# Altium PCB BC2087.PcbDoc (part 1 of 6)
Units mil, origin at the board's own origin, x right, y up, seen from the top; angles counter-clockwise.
Board outline 7401.57 x 1181.1 mil, 6 copper layers (Top Copper, Signal Layer 1, Signal Layer 2, Signal Layer 3, Signal Layer 4, Bottom Copper), stack 62.874 mil thick; 302 components, 237 nets, 1184 pads, 867 vias.
Unrouted connection lines stored in the file: 315.
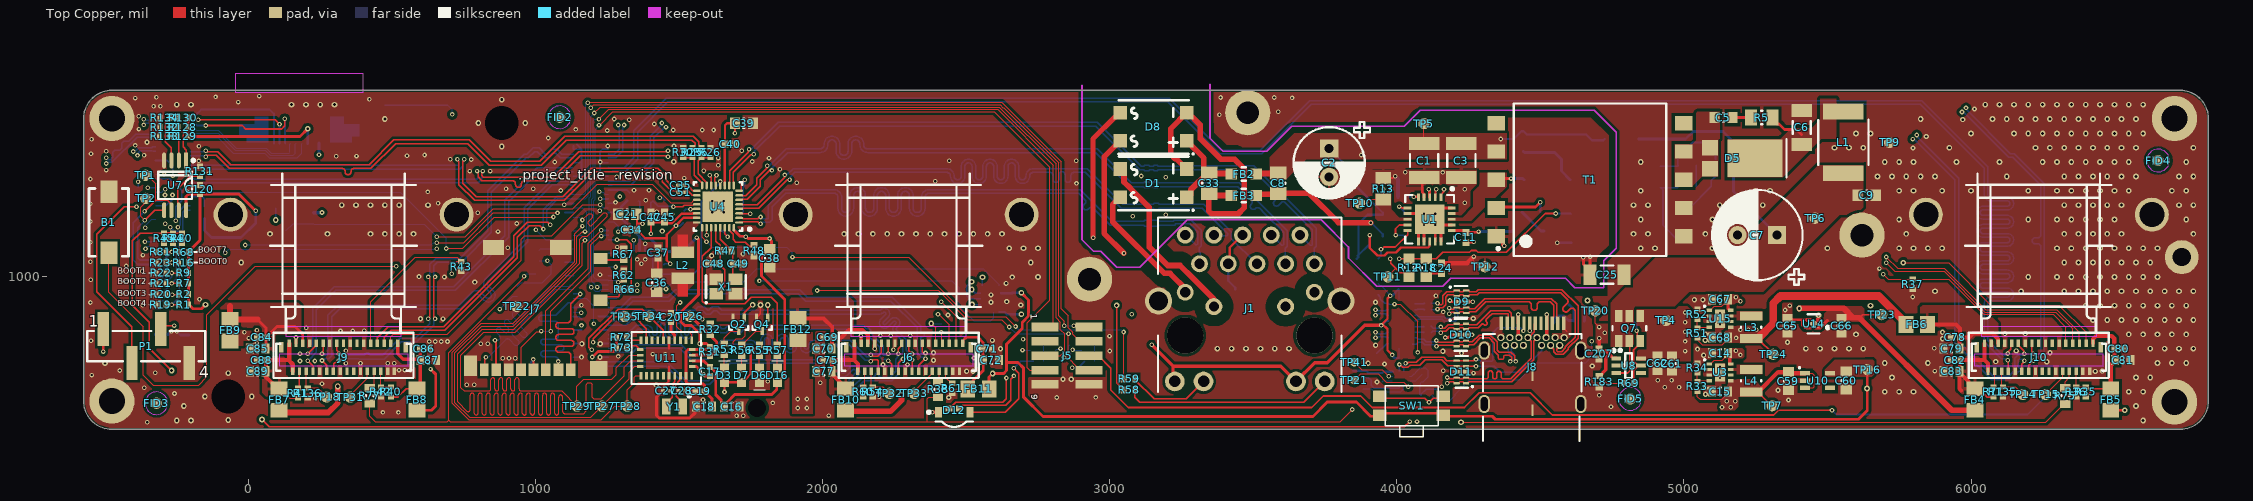
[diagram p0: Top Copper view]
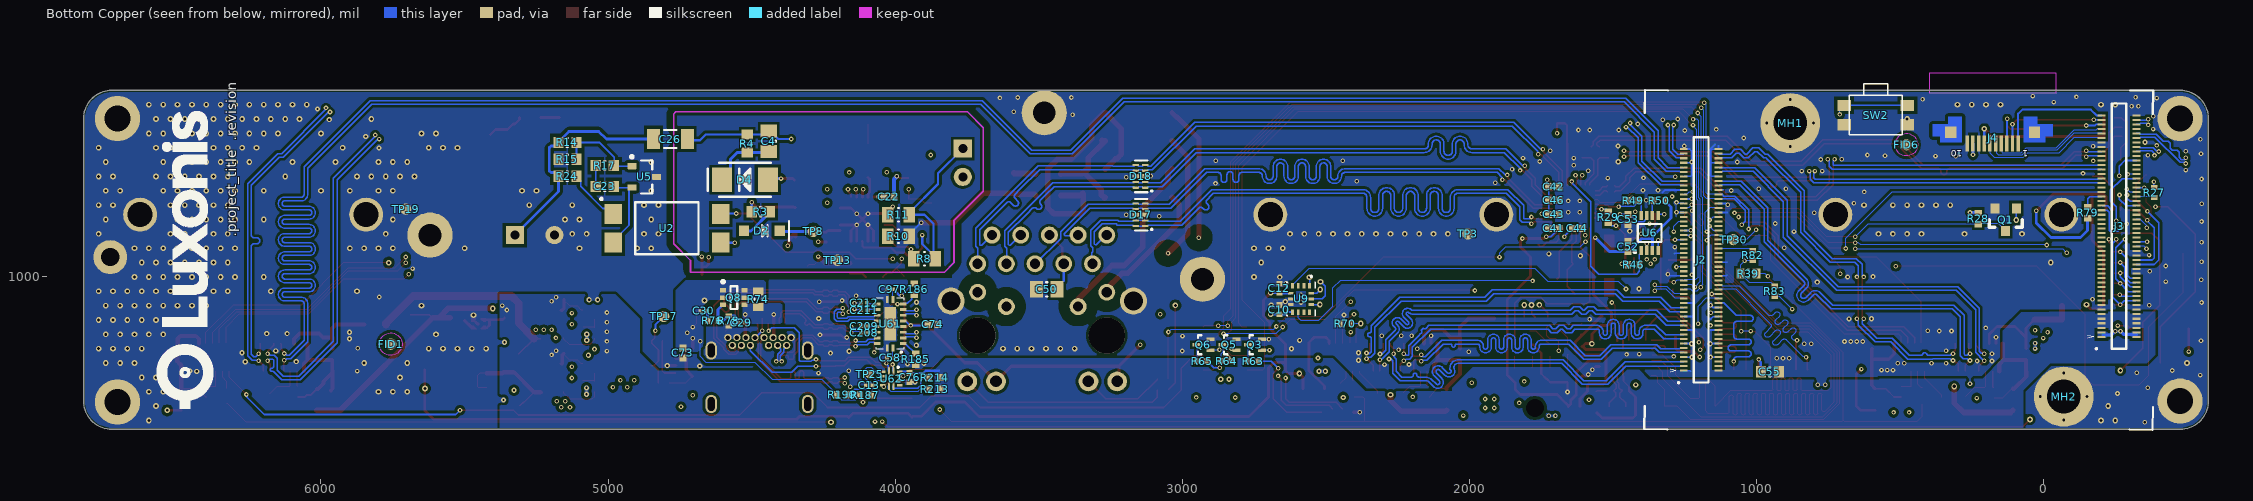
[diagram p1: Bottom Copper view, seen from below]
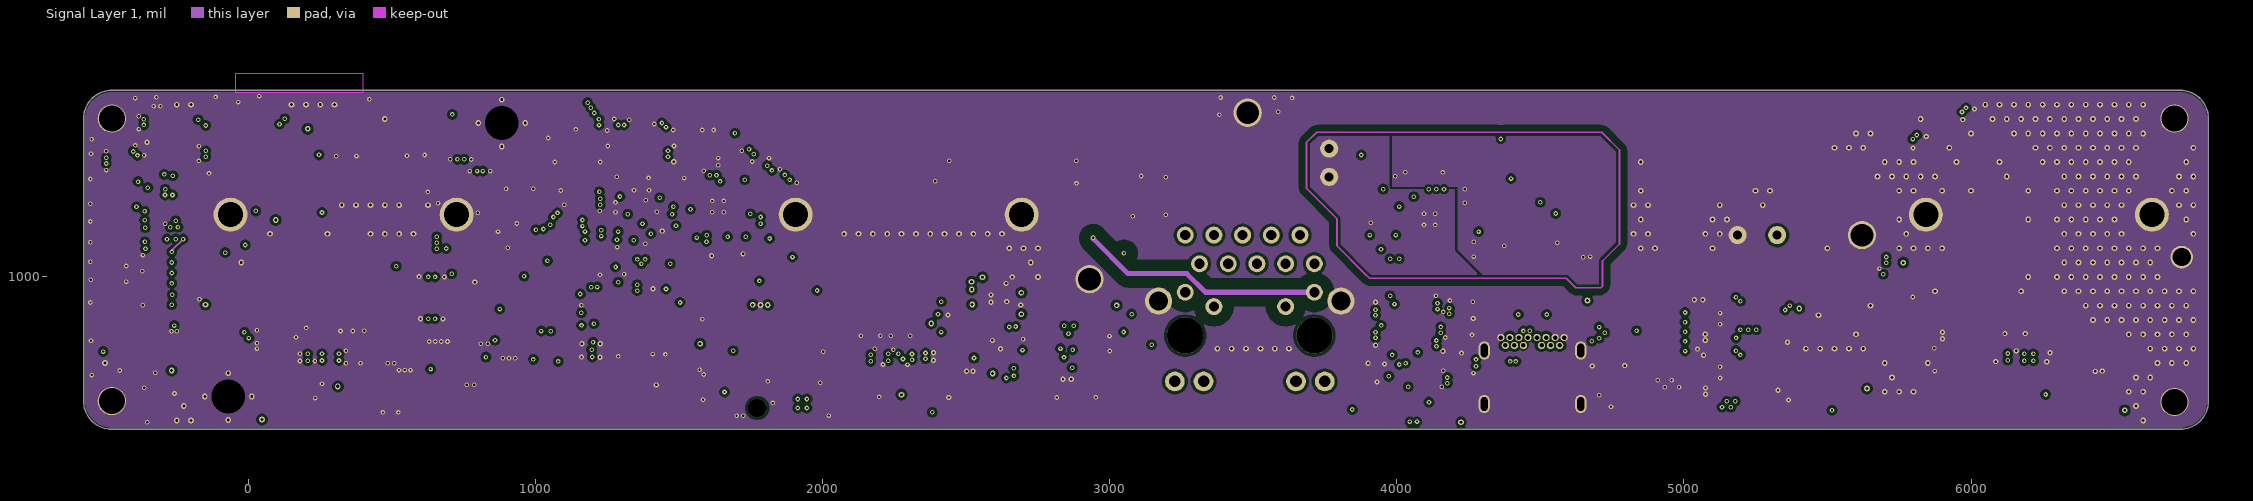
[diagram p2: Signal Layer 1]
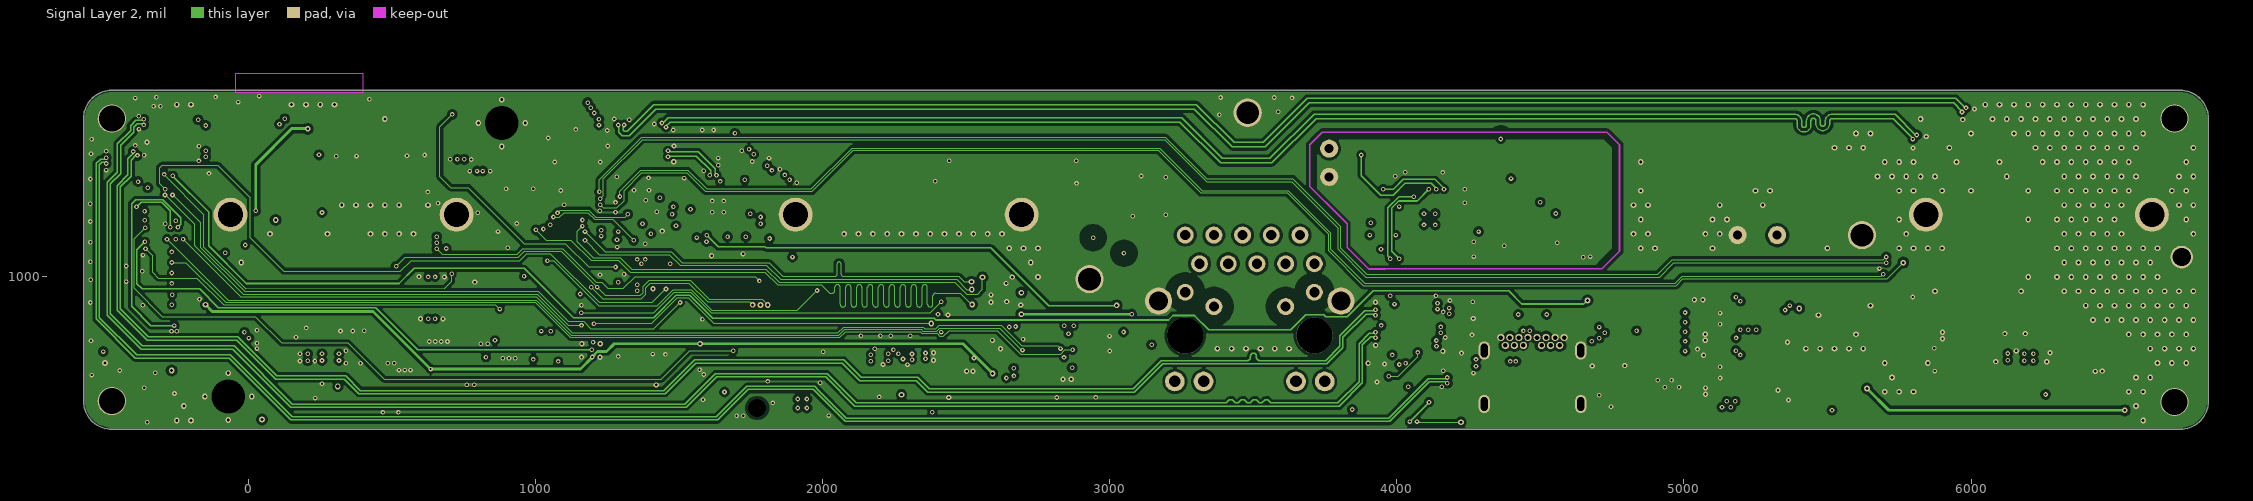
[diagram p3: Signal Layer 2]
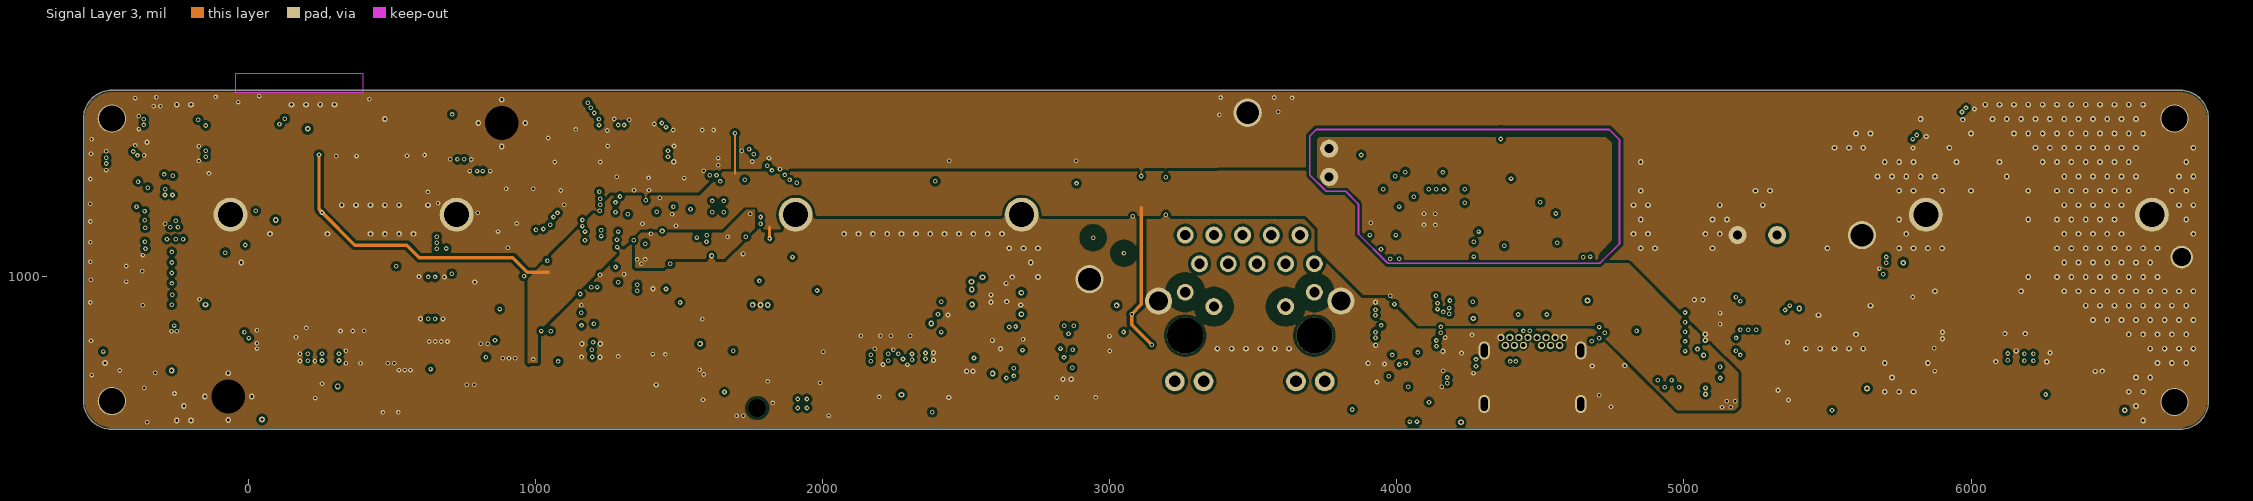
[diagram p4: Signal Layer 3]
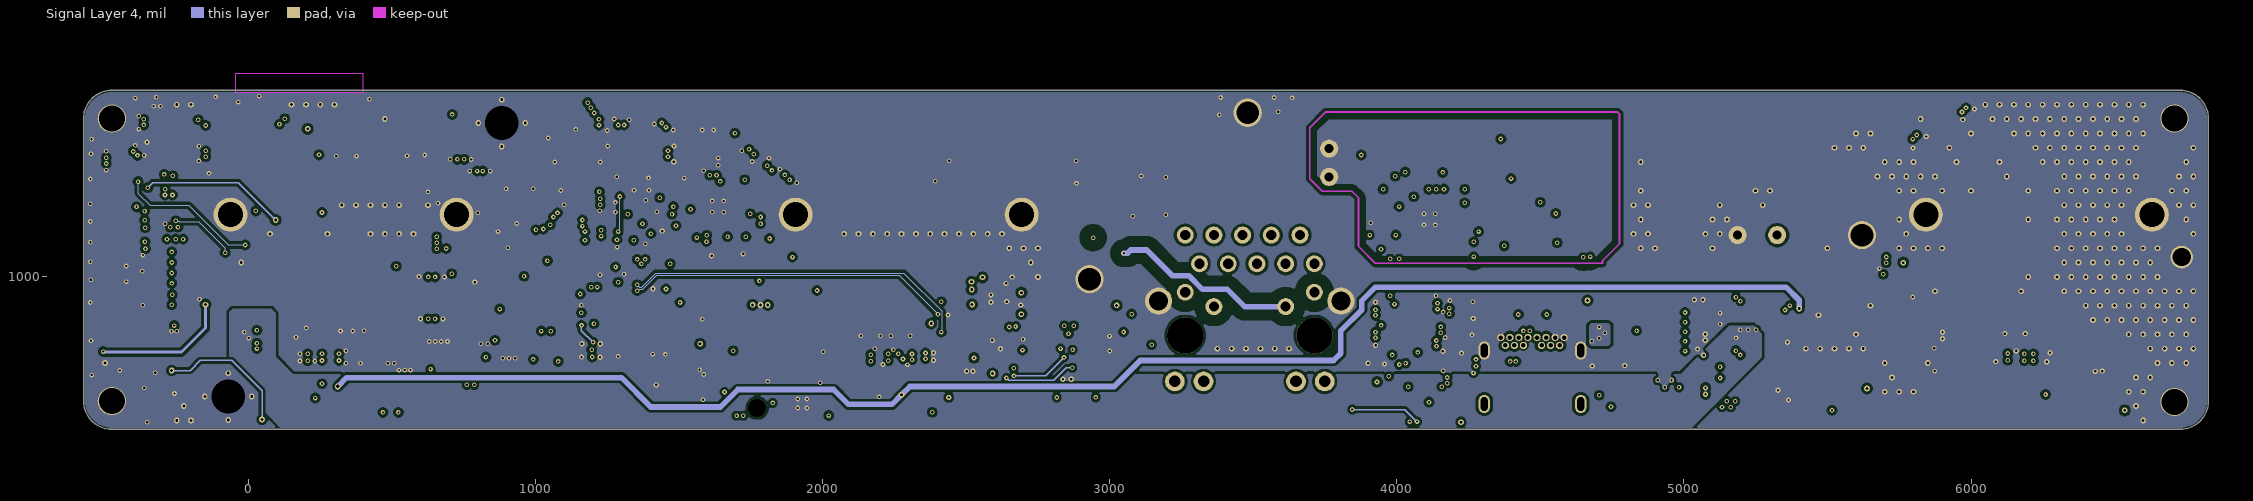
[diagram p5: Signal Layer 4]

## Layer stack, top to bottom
Top Mask: solder mask 0.5906, Solder Resist, Dk 3.8
Top Copper: signal copper 1.378
Dielectric 1: prepreg 3.937, 2313, Dk 4.05
Signal Layer 1: signal copper 0.689
Core 1: core 22.2441, FR-4, Dk 4.5
Signal Layer 2: signal copper 0.689
Dielectric 2: prepreg 5, 2116, Dk 4.25
Signal Layer 3: signal copper 0.689
Core 2: core 22.2441, FR-4, Dk 4.5
Signal Layer 4: signal copper 0.689
Dielectric 3: prepreg 3.937, 2313, Dk 4.05
Bottom Copper: signal copper 1.378
Bottom Mask: solder mask 0.5906, Solder Resist, Dk 3.8

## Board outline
-574.66,567.36 -574.66,1551.61 cw(c-476.23,1551.61) -476.23,1650.03 6728.49,1650.03 cw(c6728.49,1551.61) 6826.92,1551.61 6826.92,567.36 cw(c6728.49,567.36) 6728.49,468.93 -476.23,468.93 cw(c-476.23,567.36)

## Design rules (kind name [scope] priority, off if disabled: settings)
AssemblyTestPointUsage [All] p1: valid=2
BoardOutlineClearance [All] p1: gap=6 ignorepadtopadclearanceinfootprint=FALSE
Clearance PoE_GND [InNetClass('PoE') vs InNet('GND')] p1: gap=39.37 ignorepadtopadclearanceinfootprint=TRUE
Clearance PoE [InNetClass('PoE')] p2: gap=10 ignorepadtopadclearanceinfootprint=TRUE except(4: Track-SMDPad; 8: Arc-Track Track-Track)
Clearance general [All] p3: gap=4 ignorepadtopadclearanceinfootprint=FALSE except(10: Arc-Poly Track-Poly SMDPad-Poly THPad-Poly Via-Poly Fill-Poly Poly-Poly Poly-Region Poly-Text Poly-Hole)
ComponentClearance [All] p1: gap=0 collisioncheckmode=3 verticalgap=0 showdistances=FALSE
DiffPairsRouting 85ohm [InDifferentialPairClass('85ohm')] p1: maxlimit=10 minlimit=5 mostfreqgap=10 toplayer_mingap=5.12 toplayer_maxgap=5.12 toplayer_prefgap=5.12 toplayer_minwidth=5.12 toplayer_maxwidth=5.12 toplayer_prefwidth=5.12 midlayer2_mingap=5.89 midlayer2_maxgap=5.89 midlayer2_prefgap=5.89 midlayer2_minwidth=5.17 midlayer2_maxwidth=5.17 midlayer2_prefwidth=5.17 midlayer4_mingap=5.51 midlayer4_maxgap=5.51 midlayer4_prefgap=5.51 midlayer4_minwidth=4.33 midlayer4_maxwidth=4.33 midlayer4_prefwidth=4.33 bottomlayer_mingap=5.12 bottomlayer_maxgap=5.12 bottomlayer_prefgap=5.12 bottomlayer_minwidth=5.12 bottomlayer_maxwidth=5.12 bottomlayer_prefwidth=5.12 impedanceprofiledriven=TRUE impedanceprofileid={86B41CE9-344F-4982-9283-744235B62342} impedanceprofilevalue=90.000000 maxuncoupledlength=500
DiffPairsRouting 90ohm [InDifferentialPairClass('USB3')] p2: maxlimit=10 minlimit=5 mostfreqgap=10 toplayer_mingap=5.12 toplayer_maxgap=5.12 toplayer_prefgap=5.12 toplayer_minwidth=5.12 toplayer_maxwidth=5.12 toplayer_prefwidth=5.12 midlayer2_mingap=5.89 midlayer2_maxgap=5.89 midlayer2_prefgap=5.89 midlayer2_minwidth=5.17 midlayer2_maxwidth=5.17 midlayer2_prefwidth=5.17 midlayer4_mingap=5.51 midlayer4_maxgap=5.51 midlayer4_prefgap=5.51 midlayer4_minwidth=4.33 midlayer4_maxwidth=4.33 midlayer4_prefwidth=4.33 bottomlayer_mingap=5.12 bottomlayer_maxgap=5.12 bottomlayer_prefgap=5.12 bottomlayer_minwidth=5.12 bottomlayer_maxwidth=5.12 bottomlayer_prefwidth=5.12 impedanceprofiledriven=TRUE impedanceprofileid={86B41CE9-344F-4982-9283-744235B62342} impedanceprofilevalue=90.000000 maxuncoupledlength=500
DiffPairsRouting 100ohm [InDifferentialPairClass('100ohm')] p3: maxlimit=10.52 minlimit=5 mostfreqgap=10 toplayer_mingap=7.67 toplayer_maxgap=7.67 toplayer_prefgap=7.67 toplayer_minwidth=5.12 toplayer_maxwidth=5.12 toplayer_prefwidth=5.12 midlayer2_mingap=10.52 midlayer2_prefgap=10.52 midlayer2_minwidth=5.12 midlayer2_maxwidth=5.12 midlayer2_prefwidth=5.12 bottomlayer_mingap=7.67 bottomlayer_maxgap=7.67 bottomlayer_prefgap=7.67 bottomlayer_minwidth=5.12 bottomlayer_maxwidth=5.12 bottomlayer_prefwidth=5.12 impedanceprofiledriven=TRUE impedanceprofileid={980D49B1-4842-4C85-BE42-F6056FE0C244} impedanceprofilevalue=100.000000 maxuncoupledlength=500
FabricationTestPointUsage [All] p1: valid=2 allowmultiple=FALSE
HoleSize [All] p1: absolutevalues=TRUE maxlimit=150 minlimit=7.95 maxpercent=80.000 minpercent=20.000
HoleToHoleClearance [All] p1: gap=5 allowstackedmicrovias=FALSE
MatchedLengths ETH_GROUP [InNetClass('ETH')] p1: tolerance=1000 checknetsindiffpair=FALSE checkdiffpairvsdiffpair=TRUE checkxsignals=TRUE checkothers=TRUE usedelayunits=TRUE delaytolerance=50.000000
MatchedLengths DIFF_PAIR_100 [InDifferentialPairClass('100ohm')] p2: tolerance=1000 checknetsindiffpair=TRUE checkdiffpairvsdiffpair=FALSE checkxsignals=FALSE checkothers=FALSE usedelayunits=TRUE delaytolerance=1.000000
MatchedLengths USB [InxSignalClass('USB')] p3: tolerance=50 checknetsindiffpair=TRUE checkdiffpairvsdiffpair=FALSE checkxsignals=FALSE checkothers=FALSE usedelayunits=TRUE delaytolerance=1.000000
MatchedLengths PCIe_XSIG [InxSignalClass('XSIG_PCIe')] p4: tolerance=3.94 checknetsindiffpair=TRUE checkdiffpairvsdiffpair=FALSE checkxsignals=FALSE checkothers=FALSE usedelayunits=TRUE delaytolerance=0.500000
MatchedLengths SPI [InNetClass('QSPI')] p5: tolerance=1000 checknetsindiffpair=FALSE checkdiffpairvsdiffpair=TRUE checkxsignals=TRUE checkothers=TRUE usedelayunits=TRUE delaytolerance=10.000000
MatchedLengths SDIO [InNetClass('SDIO')] p6: tolerance=1000 checknetsindiffpair=FALSE checkdiffpairvsdiffpair=TRUE checkxsignals=TRUE checkothers=TRUE usedelayunits=TRUE delaytolerance=10.000000
MatchedLengths MIPI_A [InNetClass('MIPI_CAM_A')] p7: tolerance=1000 checknetsindiffpair=FALSE checkdiffpairvsdiffpair=TRUE checkxsignals=TRUE checkothers=TRUE usedelayunits=TRUE delaytolerance=1.000000
MatchedLengths MIPI_B [InNetClass('MIPI_CAM_B')] p8: tolerance=1000 checknetsindiffpair=FALSE checkdiffpairvsdiffpair=TRUE checkxsignals=TRUE checkothers=TRUE usedelayunits=TRUE delaytolerance=1.000000
MatchedLengths MIPI_C [InNetClass('MIPI_CAM_C')] p9: tolerance=1000 checknetsindiffpair=FALSE checkdiffpairvsdiffpair=TRUE checkxsignals=TRUE checkothers=TRUE usedelayunits=TRUE delaytolerance=1.000000
MinimumSolderMaskSliver USB3_Connector [HasFootprint('105450-0101')  OR HasFootprint('CX80B1-24P') OR HasFootprint('TPD4E02B04DQAR')  OR HasFootprint('RTL8111HX-CG')  or HasFootprint('632723100011')] p1: minsoldermaskwidth=0.1
MinimumSolderMaskSliver RTL8111 [HasFootprint('CX80B1-24P')] p2: minsoldermaskwidth=0.1
MinimumSolderMaskSliver [All] p3: minsoldermaskwidth=2
PlaneConnect [All] p1: pad.planeconnectstyle=Relief pad.reliefexpansion=20 pad.reliefentries=4 pad.reliefconductorwidth=10 pad.reliefairgap=10 via.planeconnectstyle=Direct via.reliefexpansion=20 via.reliefentries=4 via.reliefconductorwidth=10 via.reliefairgap=10
PolygonConnect DirectConnect [InPolygonClass('DirectConnectPoly')] p1: connectstyle=Direct reliefconductorwidth=10 reliefentries=4 polygonreliefangle="90 Angle" airgapwidth=10
PolygonConnect OuterLayerGND_PolyClass [InPolygonClass('OuterLayerGND')] p2: thpad.connectstyle=Relief thpad.reliefconductorwidth=10 thpad.reliefentries=4 thpad.polygonreliefangle="90 Angle" thpad.airgapwidth=10 smdpad.connectstyle=Relief smdpad.reliefconductorwidth=10 smdpad.reliefentries=4 smdpad.polygonreliefangle="90 Angle" smdpad.airgapwidth=10 via.connectstyle=Direct via.reliefconductorwidth=10 via.reliefentries=4 via.polygonreliefangle="90 Angle" via.airgapwidth=10
PolygonConnect PoE_Poly [InPolygonClass('PoE_Poly')] p3: thpad.connectstyle=Direct thpad.reliefconductorwidth=10 thpad.reliefentries=4 thpad.polygonreliefangle="90 Angle" thpad.airgapwidth=10 smdpad.connectstyle=Relief smdpad.reliefconductorwidth=10 smdpad.reliefentries=4 smdpad.polygonreliefangle="90 Angle" smdpad.airgapwidth=10 via.connectstyle=Direct via.reliefconductorwidth=10 via.reliefentries=4 via.polygonreliefangle="90 Angle" via.airgapwidth=10
PolygonConnect Default [All] p4: thpad.connectstyle=Relief thpad.reliefconductorwidth=10 thpad.reliefentries=4 thpad.polygonreliefangle="90 Angle" thpad.airgapwidth=10 smdpad.connectstyle=Relief smdpad.reliefconductorwidth=10 smdpad.reliefentries=4 smdpad.polygonreliefangle="90 Angle" smdpad.airgapwidth=10 via.connectstyle=Direct via.reliefconductorwidth=10 via.reliefentries=4 via.polygonreliefangle="90 Angle" via.airgapwidth=10
RoutingVias [All] p1: holewidth=10 width=20 viastyle="Through Hole" minholewidth=8 minwidth=16 maxholewidth=1000 maxwidth=1000 viatemplateguid#1={7D568E1B-5E6B-4AC2-AD27-6C01C0E9FBBD} viatemplatename#1=v41h20m0mx0
SilkToSilkClearance [All] p1: silktosilkclearance=1
SilkToSolderMaskClearance SilkscreenOverComponentException [InComponent('U15')] p1: minsilkscreentomaskgap=3 clearancetoexposedcopper=TRUE
SilkToSolderMaskClearance SilkscreenOverComponentPads [IsPad] p2: minsilkscreentomaskgap=3 clearancetoexposedcopper=TRUE
SolderMaskExpansion [All] p1: expansion=2 istentingtop=FALSE
UnRoutedNet [All] p1: checkbadconnections=TRUE
Width "Schematic Width Constraint_1" [InNetClass('PoE')] p1: maxlimit=50 minlimit=4 preferedwidth=15
Width [All] p2: maxlimit=100 minlimit=4 preferedwidth=5
19 further rules are at their usual default settings.

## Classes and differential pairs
component class U_DM2077_RIGHT_AR0234: C84 C85 C86 C87 C88 C89 FB7 FB8 FB9 J9 R40 R41 R42 R43 R136 TP18 TP31
component class U_DM2077_LEFT_AR0234: C78 C79 C80 C81 C82 C83 FB4 FB5 FB6 J10 R35 R36 R37 R38 R39 R71 R75 R77 R135 TP14 TP15
component class U_BO2077_POWER_GEN: C14 C15 C59 C60 C61 C62 C65 C66 C67 C68 L3 L4 Q7 R33 R34 R51 R52 R69 TP4 TP7 TP16 TP17 TP20 TP23 TP24 U3 U8 U10 U14 U15
component class U_BC2088_RJ45: C50 D1 D8 D16 D17 D18 J1 R57 R58 R59
component class U_BC2077_USB: C13 C29 C30 C58 C73 C74 C76 C97 C207 C208 C209 C211 C212 D9 D10 D11 J8 Q8 R74 R76 R78 R183 R185 R186 R187 R190 R213 R214 TP21 TP25 TP41 U61 U62
component class U_BC2077_IMU: C10 C12 C16 C17 C18 C19 C20 C27 C28 R31 R32 R72 R73 TP26 TP34 TP35 U9 U11 Y1
component class U_BC2077_ETH_PCIE_PHY: C21 C34 C35 C36 C37 C38 C39 C40 C41 C42 C43 C44 C45 C46 C47 C48 C49 C51 C52 C53 L2 Q1 R6 R25 R26 R28 R29 R30 R46 R47 R48 R49 R50 U4 U6 X1
component class U_BC2077_EEPROM: C120 R128 R129 R130 R131 R132 R133 R134 U7
component class U_BC2077_BOOT_JTAG_AUX: C55 D3 D6 D7 D12 J4 J5 J7 P1 Q2 Q3 Q4 Q5 Q6 R53 R55 R56 R63 R64 R65 R66 R67 TP1 TP2
component class U_BC2077__MID_AR0234: C69 C70 C71 C72 C75 C77 FB10 FB11 FB12 J6 R54 R60 R61 R70 TP32 TP33
component class U_BC20__PoE_Si3404: C1 C2 C3 C4 C5 C6 C7 C8 C9 C11 C22 C23 C24 C25 C26 C33 D2 D4 D5 FB2 FB3 L1 R3 R4 R5 R8 R10 R11 R12 R13 R14 R15 R17 R18 R24 T1 TP5 TP6 TP8 TP9 TP10 TP11 TP12 TP13 U1 U2 U5
net class PCIe: BRIDGE_REFCLK_N BRIDGE_REFCLK_P CLK_N CLK_P SDS_RXD1_N SDS_RXD1_P SDS_RXD_N SDS_RXD_P SDS_TXD_N SDS_TXD_P
polygon class PoE_Poly: VNEG_IN_L01_P432 VNEG_L01_P434 VNEG_L04_P456 VPOS_IN_L01_P431
polygon class DirectConnectPoly: 1V2_L01_P021_DC 1V2_L01_P061_DC 1V2_L01_P062_DC 1V2_L05_P042 1V8_L01_P023_DC 2V8_L01_P023_DC 3V3_L3_DC 3V3_TL_DC 5V_POE_L01_P041_DC GND_L01_P071 GND_L02_P037 GND_L03_P036 GND_L04_P060 GND_L05_P051 GND_L06_P069 ISNS_L01_P005_DC NetC6_2_TL_DC NETL3_1_L01_P025_DC NETL4_1_L01_P025_DC PCIE_1V0_L01_P020_DC PCIE_1V0_L01_P058_DC PCIE_1V0_L04_P057_DC REGOUT_TL_DC SWO_L01_P004_DC VBUS_L01_P043_DC VBUS_L05_P042_DC VBUS_L06_P033 VBUSIN_L06_P032 VDD_5V_L01_P044_DC VDD_5V_L01_P046_DC VDD_5V_L01_P047_DC VDD_5V_L01_P048_DC VDD_5V_L06_P050_DC VNEG_L02_P031 VNEG_L06_P068 VPOS_L01_P002_DC VSEC_L01_P007_DC VSS_L01_P003_DC VSS_L02_P030
net class Power_trace: 1V2_CAM_M 1V2_L 1V2_R 1V8_CAM_M 1V8_L 1V8_R 2V8_CAM_M 2V8_L 2V8_R 5V_PoE VBUS VBUSIN VDD_5V
net class PoE: CT1 CT2 SP1 SP2 SWO VNEG VNEG_IN VPOS VPOS_IN VSS
component class TopLevel: FID1 FID2 FID3 FID4 FID5 FID6 MH1 MH2 TP3 TP19 TP22
differential pair class USB3: RXB RXC TXB TXB1 TXC TXC1 USB_D USB_RX USB_TX
net class USB: USB_D_N USB_D_P USB_RX_N USB_RX_P USB_TX_N USB_TX_P
net class SDIO: sd_hst0_clk sd_hst0_cmd sd_hst0_dat_0 sd_hst0_dat_1 sd_hst0_dat_2 sd_hst0_dat_3
net class QSPI: SPI_BMI270_CS_1V8 SPI_BNO08x_CS_1V8 SPI_MISO_1V8 SPI_MOSI_1V8 SPI_SCK_1V8 SPI_SIO2 SPI_SIO3
net class MIPI_CAM_C: MIPI_RX3_C_N MIPI_RX3_C_P MIPI_RX3_D0_N MIPI_RX3_D0_P MIPI_RX3_D1_N MIPI_RX3_D1_P
net class MIPI_CAM_B: MIPI_RX2_C_N MIPI_RX2_C_P MIPI_RX2_D0_N MIPI_RX2_D0_P MIPI_RX2_D1_N MIPI_RX2_D1_P
net class MIPI_CAM_A: MIPI_RX4_C_N MIPI_RX4_C_P MIPI_RX4_D0_N MIPI_RX4_D0_P MIPI_RX4_D1_N MIPI_RX4_D1_P MIPI_RX5_D0_N MIPI_RX5_D0_P MIPI_RX5_D1_N MIPI_RX5_D1_P
differential pair class 100ohm: BRIDGE_REFCLK BRIDGE_REFCLK1 CLK MD1 MD1_1 MD2 MD2_1 MD3 MD3_1 MD4 MD4_1 MIPI_RX2_C MIPI_RX2_D0 MIPI_RX2_D1 MIPI_RX3_C MIPI_RX3_D0 MIPI_RX3_D1 MIPI_RX4_C MIPI_RX4_D0 MIPI_RX4_D1 MIPI_RX5_D0 MIPI_RX5_D1 SDS_IO_CLKI SDS_IO_CLKI1 SDS_RXD SDS_RXD1 SDS_TXD
component class U_CONNECTOR_B: J3 q R1 R2 R7 R9 R16 R19 R20 R21 R22 R23 R27 R44 R45 R68 R79 R80 R81 R83 SW1
component class U_CONNECTOR_A: B1 J2 R62 R82 SW2 TP27 TP28 TP29 TP30
net class ETH: MD1_N MD1_P MD2_N MD2_P MD3_N MD3_P MD4_N MD4_P
differential pair CLK: +CLK_P -CLK_N
differential pair SDS_RXD1: +SDS_RXD1_P -SDS_RXD1_N
differential pair USB_TX: +USB_TX_P -USB_TX_N
differential pair TXC: +TXC_P -TXC_N
differential pair TXC1: +TXC1_P -TXC1_N
differential pair TXB: +TXB_P -TXB_N
differential pair TXB1: +TXB1_P -TXB1_N
differential pair RXC: +RXC_P -RXC_N
differential pair RXB: +RXB_P -RXB_N
differential pair BRIDGE_REFCLK: +BRIDGE_REFCLK_P -BRIDGE_REFCLK_N
differential pair USB_RX: +USB_RX_P -USB_RX_N
differential pair USB_D: +USB_D_P -USB_D_N
differential pair SDS_TXD: +SDS_TXD_P -SDS_TXD_N
differential pair SDS_RXD: +SDS_RXD_P -SDS_RXD_N
differential pair MIPI_RX5_D1: +MIPI_RX5_D1_P -MIPI_RX5_D1_N
differential pair MIPI_RX5_D0: +MIPI_RX5_D0_P -MIPI_RX5_D0_N
differential pair MIPI_RX4_D1: +MIPI_RX4_D1_P -MIPI_RX4_D1_N
differential pair MIPI_RX4_D0: +MIPI_RX4_D0_P -MIPI_RX4_D0_N
differential pair MIPI_RX4_C: +MIPI_RX4_C_P -MIPI_RX4_C_N
differential pair MIPI_RX3_D1: +MIPI_RX3_D1_P -MIPI_RX3_D1_N
differential pair MIPI_RX3_D0: +MIPI_RX3_D0_P -MIPI_RX3_D0_N
differential pair MIPI_RX3_C: +MIPI_RX3_C_P -MIPI_RX3_C_N
differential pair MIPI_RX2_D1: +MIPI_RX2_D1_P -MIPI_RX2_D1_N
differential pair MIPI_RX2_D0: +MIPI_RX2_D0_P -MIPI_RX2_D0_N
differential pair MIPI_RX2_C: +MIPI_RX2_C_P -MIPI_RX2_C_N
differential pair MD4: +MD4_P -MD4_N
differential pair MD3: +MD3_P -MD3_N
differential pair MD2: +MD2_P -MD2_N
differential pair MD1: +MD1_P -MD1_N

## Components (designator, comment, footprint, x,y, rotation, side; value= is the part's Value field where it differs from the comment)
B1 "Off-Mom, 50mA" DTSM-32N-V -487,1190.3 r270 top
C1 "1uF 1210" CAPC1210(3225)280_N 4094.62,1405.51 r90 top
C2 "12uF 6.3mm" EEU-FC2A120 3764.34,1397.64 r270 top
C3 "1uF 1210" CAPC1210(3225)280_N 4224.54,1405.51 r90 top
C4 "0.1UF 0805" CAPC0805(2012)145_N 4440.52,1472.44 r90 bottom
C5 "1nF 0603 C0G" CAPC0603(1608)100_N 5137.8,1555.12 r180 top
C6 "100uF 1206" CAPC1206(3216)190_N 5410.63,1520.67 r270 top
C7 "1000uF 8mm" ECA-0JM102 5255.91,1145.67 r180 top
C8 "0.1UF 0805" CAPC0805(2012)145_N 3586.61,1326.77 r90 top
C9 "22NF 0603" CAPC0603(1608)100_N 5636.5,1285 r180 top
C10 "0.1uF 0402" CAPC0402(1005)70_L 2661.42,885.83 r270 bottom
C11 "1uF 0402" CAPC0402(1005)70_N 4240.29,1137.8 r90 top
C12 "0.1uF 0402" CAPC0402(1005)70_L 2661.42,960.63 r270 bottom
C13 "1uF 0201" CAPC0201(0603)33_L 4090.55,622.49 r180 bottom
C14 "10uF 0603" CAPC0603(1608)100_L 5125.98,734.55 r0 top
C15 "22uF 0603" CAPC0603(1608)100_L 5125.98,600.69 r0 top
C16 "GRM188R61A106ME69D" CAPC0603(1608)100_L 1683,548.35 r180 top value=10µF
C17 "GRM155R71A104JA01D" CAPC0402(1005)70_L 1607,670 r90 top value=100nF
C18 "GRM188R61A106ME69D" CAPC0603(1608)100_L 1586.76,548.35 r0 top value=10µF
C19 "GRM155R71A104JA01D" CAPC0402(1005)70_L 1573,601 r0 top value=100nF
C20 "GRM155R71A104JA01D" CAPC0402(1005)70_L 1471,859 r90 top value=100nF
C21 "4.7uF 0603" CAPC0603(1608)100_N 1319.2,1218.63 r0 top
C22 "0.1uF 0402" CAPC0402(1005)60_N 4021.78,1279.53 r0 bottom
C23 "2.2nF 0603" CAPC0603(1608)100_N 5011.65,1314.96 r0 bottom
C24 "10nF 0402" CAPC0402(1005)60_N 4156.26,1030.19 r270 top
C25 "1nF 1206" CAPC1206(3216)190_N 4732.28,1007.87 r0 top
C26 "1nF 1206" CAPC1206(3216)190_N 4783.04,1480.31 r0 bottom
C27 "GRM0335C1E180FA01D" CAPC0201(0603)33_L 1454.55,603.1 r0 top value=18pF
C28 "GRM0335C1E180FA01D" CAPC0201(0603)33_L 1508.72,603.1 r180 top value=18pF
C29 "1uF 0201" CAPC0201(0603)33_L 4535.43,840 r180 bottom
C30 "0.1uF 0201" CAPC0201(0603)33_L 4666.14,881.89 r0 bottom
C33 "0.1UF 0805" CAPC0805(2012)145_N 3346.46,1326.77 r90 top
C34 "0.1uF 0402" CAPC0402(1005)70_N 1334.94,1163.86 r0 top
C35 "0.1uF 0201" CAPC0201(0603)33_L 1506.16,1318.86 r0 top
C36 "4.7uF 0603" CAPC0603(1608)100_N 1422.03,979.87 r90 top
C37 "0.1uF 0402" CAPC0402(1005)70_N 1426.4,1083.66 r270 top
C38 "4.7uF 0603" CAPC0603(1608)100_N 1814.96,1064.74 r90 top
C39 "4.7uF 0603" CAPC0603(1608)100_N 1725.53,1535 r180 top
C40 "0.1uF 0402" CAPC0402(1005)70_N 1677.29,1462.25 r180 top
C41 "0.1uF 0402" CAPC0402(1005)70_N 1705.92,1169.33 r180 bottom
C42 "0.1uF 0402" CAPC0402(1005)70_N 1705.92,1314.27 r0 bottom
C43 "0.1uF 0402" CAPC0402(1005)70_N 1705.8,1218.1 r0 bottom
C44 "0.1uF 0402" CAPC0402(1005)70_N 1623.24,1169.33 r0 bottom
C45 "0.1uF 0402" CAPC0402(1005)70_N 1449.12,1208.38 r270 top
C46 "1uF 0402" CAPC0402(1005)70_N 1705.8,1267.39 r0 bottom
C47 "1uF 0402" CAPC0402(1005)70_N 1401.1,1208.45 r270 top
C48 "27pF 0402" CAPC0402(1005)60_N 1620.47,1045.98 r0 top
C49 "27pF 0402" CAPC0402(1005)60_N 1704.92,1045.76 r180 top
C50 "0.1UF 0805" CAPC0805(2012)145_N 3472.44,956.69 r180 bottom
C51 "0.1uF 0201" CAPC0201(0603)33_L 1506.16,1295.24 r0 top
C52 "0.1uF 0402" CAPC0402(1005)70_N 1446.73,1105.9 r270 bottom
C53 "0.1uF 0402" CAPC0402(1005)70_N 1446.73,1200.39 r90 bottom
C55 "4.7uF 0603" CAPC0603(1608)100_N 952.76,669.69 r0 bottom
C58 "0.1uF 0201" CAPC0201(0603)33_L 4017.36,717.61 r180 bottom
C59 "10uF 0603" CAPC0603(1608)100_N 5364.17,637.19 r90 top
C60 "10uF 0603" CAPC0603(1608)100_N 5564.96,638.94 r90 top
C61 "22uF 0603" CAPC0603(1608)100_L 4957.96,698.27 r270 top
C62 "22uF 0603" CAPC0603(1608)100_L 4908.26,699.13 r270 top
C65 "10uF 0603" CAPC0603(1608)100_L 5360.38,829.72 r90 top
C66 "10uF 0603" CAPC0603(1608)100_L 5549.21,829.72 r90 top
C67 "10uF 0603" CAPC0603(1608)100_L 5125.98,922.24 r0 top
C68 "22uF 0603" CAPC0603(1608)100_L 5125.98,788.69 r0 top
C69 "0.1uF 0402" CAPC0402(1005)70_L 2017.41,789.59 r0 top
C70 "10uF 0603" CAPC0603(1608)100_L 2004.04,750.22 r0 top
C71 "0.1uF 0402" CAPC0402(1005)70_L 2573.59,750.22 r180 top
C72 "10uF 0603" CAPC0603(1608)100_L 2586.79,710.55 r180 top
C73 "10uF 0402" CAPC0402(1005)70_N 4739.67,735 r90 bottom
C74 "10uF 0402" CAPC0402(1005)70_N 3868.11,834.65 r0 bottom
C75 "0.1uF 0402" CAPC0402(1005)70_L 2017.41,710.55 r0 top
C76 "10uF 0402" CAPC0402(1005)70_L 3949.51,649.89 r90 bottom
C77 "10uF 0603" CAPC0603(1608)100_L 2004.04,671.48 r0 top
C78 "0.1uF 0402" CAPC0402(1005)70_L 5945.56,789.59 r0 top
C79 "10uF 0603" CAPC0603(1608)100_L 5932.18,750.22 r0 top
C80 "0.1uF 0402" CAPC0402(1005)70_L 6514.97,750.22 r180 top
C81 "10uF 0603" CAPC0603(1608)100_L 6528.74,710.55 r180 top
C82 "0.1uF 0402" CAPC0402(1005)70_L 5945.96,710.55 r0 top
C83 "10uF 0603" CAPC0603(1608)100_L 5932.18,671.48 r0 top
C84 "0.1uF 0402" CAPC0402(1005)70_L 45.69,789.59 r0 top
C85 "10uF 0603" CAPC0603(1608)100_L 31.91,750.22 r0 top
C86 "0.1uF 0402" CAPC0402(1005)70_L 612.2,750.22 r180 top
C87 "10uF 0603" CAPC0603(1608)100_L 626.11,710.55 r180 top
C88 "0.1uF 0402" CAPC0402(1005)70_L 45.69,710.55 r0 top
C89 "10uF 0603" CAPC0603(1608)100_L 31.91,671.48 r0 top
C97 "0.1uF 0201" CAPC0201(0603)33_L 4017.9,956.69 r180 bottom
C120 "0.1uF 0402" CAPC0402(1005)70_L -169.29,1304.88 r270 top
C207 "10uF 0402" CAPC0402(1005)70_N 4704.72,731.79 r90 top
C208 "0.1uF 0201" CAPC0201(0603)33_L 4107.13,805.2 r180 bottom
C209 "0.1uF 0201" CAPC0201(0603)33_L 4107.13,828.82 r180 bottom
C211 "0.1uF 0201" CAPC0201(0603)33_L 4107.91,884.13 r180 bottom
C212 "0.1uF 0201" CAPC0201(0603)33_L 4108.31,909.45 r180 bottom
D1 "CD-HD01" CD-H01 3151.93,1326.77 r270 top
D2 "1N4148W" 1N4148W-7-F 4464.14,1160.43 r0 bottom
D3 "ORANGE 0603" SML_D1xx8W 1657.48,657.48 r270 top
D4 "RS1B" RS1B 4523.19,1338.58 r180 bottom
D5 "PDS1040" PDS1040-13 5203.7,1413.39 r180 top
D6 "RED 0603" SML_D1xx8W 1779.53,657.48 r90 top
D7 "ORANGE 0603" SML_D1xx8W 1717.63,657.48 r270 top
D8 "CD-HD01" CD-H01 3151.93,1522.98 r270 top
D9 "TPD4E02B04DQAR" TPD4E02B04DQAR 4225.46,913.39 r270 top
D10 "TPD4E02B04DQAR" TPD4E02B04DQAR 4224.41,797.92 r270 top
D11 "TPD4E02B04DQAR" TPD4E02B04DQAR 4224.41,669.29 r90 top
D12 "155124M173200" FP-155124M173200-MFG 2458,509 r0 top
D16 "GREEN 0603" SML_D1xx8W 1841.97,657.48 r270 top
D17 "TPD4E02B04DQAR" TPD4E02B04DQAR 3144.98,1216.54 r90 bottom
D18 "TPD4E02B04DQAR" TPD4E02B04DQAR 3144.98,1350.39 r90 bottom
FB2 "700R/150Mhz" 742792040 3466.42,1358.27 r0 top
FB3 "700R/150Mhz" 742792040 3466.42,1283.46 r0 top
FB4 "600R/100MHz" 2508056017Y2 6013.85,572.83 r90 top
FB5 "600R/100MHz" 2508056017Y2 6486.76,572.83 r90 top
FB6 "600R/100MHz" 2508056017Y2 5811.02,834.65 r0 top
FB7 "600R/100MHz" 2508056017Y2 106.3,572.83 r90 top
FB8 "600R/100MHz" 2508056017Y2 586.61,572.83 r90 top
FB9 "600R/100MHz" 2508056017Y2 -64.47,814.27 r90 top
FB10 "600R/100MHz" 2508056017Y2 2079.46,572.83 r90 top
FB11 "600R/100MHz" 2508056017Y2 2542.21,610.24 r180 top
FB12 "600R/100MHz" 2508056017Y2 1913.44,818.33 r90 top
FID1 "FIDUCIAL_ROUND_1MM" FIDUCIAL_ROUND_1MM 5756.89,765.75 r90 bottom
FID2 "FIDUCIAL_ROUND_1MM" FIDUCIAL_ROUND_1MM 1083.66,1556.1 r90 top
FID3 "FIDUCIAL_ROUND_1MM" FIDUCIAL_ROUND_1MM -320.87,560.04 r90 top
FID4 "FIDUCIAL_ROUND_1MM" FIDUCIAL_ROUND_1MM 6652.02,1405.51 r90 top
FID5 "FIDUCIAL_ROUND_1MM" FIDUCIAL_ROUND_1MM 4812.99,574.8 r90 top
FID6 "FIDUCIAL_ROUND_1MM" FIDUCIAL_ROUND_1MM 477.36,1460.63 r90 bottom
J1 "802.3af PoE" TRJG0926HENL 3487.6,795.73 r0 top locked
J2 "DF40HC(3.0)-100DS-0.4V_SoM-PRO_A" CON_A_BW2099_SoM_DF40HC-3.0-100DS-0.4V_minpad 503.35,1059.06 r180 bottom locked
J3 "DF40HC(3.0)-100DS-0.4V_SoM-PRO_B" CON_B_BW2099_SoM_DF40HC-3.0-100DS-0.4V_minpad 504.33,1059.06 r180 bottom locked
J4 "SFV10R-2STE1HLF Top Contact" SFV10R-2STE1HLF 176.87,1484.47 r0 bottom
J5 "20021121-00010T1LF" 20021121-00010T1LF 2851.38,725.39 r270 top
J6 "FH26W-33S-0.3SHW(60)" AC-PY003-OV9282 2298.58,1108.27 r0 top locked
J7 "uSD push/pull" 104031-0811 999.73,889.27 r0 top locked
J8 "632723100011" 632723100011 4472.44,604.62 r0 top locked
J9 "FH26W-33S-0.3SHW(60)" AC-PY003-OV9282 330.08,1108.27 r0 top locked
J10 "FH26W-33S-0.3SHW(60)" AC-PY003-OV9282 6235.59,1108.27 r0 top locked
L1 "1uH 2.9A" DO1608C-102MLx 5555.12,1468.5 r270 top
L2 "2.2uH 0.61A 97mR" LQH32NH2R2J23L 1512.32,1040.61 r270 top
L3 "1uH, 3.2A, 20%" DFE252012P-1R0M=P2 5234.25,824.8 r270 top
L4 "1uH, 3.2A, 20%" DFE252012P-1R0M=P2 5234.25,638.1 r270 top
MH1 "M2, 3MM steel spacer on M2.5 mounting pad" 9774030243R 882.03,1535.86 r180 bottom
MH2 "M2, 3MM steel spacer on M2.5 mounting pad" 9774030243R -70.72,583.1 r180 bottom
P1 "61000418321" 61000418321 -356.43,759 r0 top
Q1 "PREBIAS'd DDTC114YCA-7-F" DDTC114YCA-7-F 131.93,1199.37 r0 bottom
Q2 "RE1C002UNTCL" RE1C002UNTCL 1707,835 r180 top
Q3 "RE1C002UNTCL" RE1C002UNTCL 2746.65,763.78 r90 bottom
Q4 "RE1C002UNTCL" RE1C002UNTCL 1789,835 r180 top
Q5 "RE1C002UNTCL" RE1C002UNTCL 2835.63,763.78 r90 bottom
Q6 "RE1C002UNTCL" RE1C002UNTCL 2926.18,763.78 r90 bottom
Q7 "IRLTS2242TRPBF" TSOP-6-MFG 4810.04,820.87 r90 top
Q8 "NTJS4151PT1G" ONSC-SC70-6-419B-02_W_V 4562,928 r180 bottom
R1 "RC0402FR-1310KL" RESC0402(1005)_L -226.38,903.6 r0 top value=10k
R2 "RC0402FR-1310KL" RESC0402(1005)_L -226.38,939.96 r0 top value=10k
R3 "10R 0603" RESC0603(1608)_N 4468.08,1227.36 r0 bottom
R4 "18K 0603" RESC0603(1608)_N 4515.32,1464.57 r90 bottom
R5 "6.8R 0805" RESC0805(2012)_N 5271.65,1555.12 r0 top
R6 "22R 0402" RESC0402(1005)_L 1577.24,1433.65 r90 top
R7 "RC0402FR-1310KL" RESC0402(1005)_L -226.38,977.36 r0 top value=10k
R8 "88.7K 0805" RESC0805(2012)_N 3897.77,1062.99 r0 bottom
R9 "RC0402FR-1310KL" RESC0402(1005)_L -226.38,1013.78 r0 top value=10k
R10 "48.7R 0805" RESC0805(2012)_N 3988.32,1141.73 r0 bottom
R11 "24.3k 0805" RESC0805(2012)_N 3988.32,1216.54 r0 bottom
R12 "4.99k 0603" RESC0603(1608)_N 4042.09,1031.5 r270 top
R13 "0.62R 0805" RESC0805(2012)_N 3952.76,1307.09 r90 top
R14 "36.5k 0603" RESC0603(1608)_N 5141.73,1468.5 r0 bottom
R15 "12.1k 0603" RESC0603(1608)_N 5141.73,1409.45 r180 bottom
R16 "RC0402FR-1310KL" RESC0402(1005)_L -226.38,1050.2 r0 top value=10k
R17 "0R 0603" RESC0603(1608)_N 5011.65,1387.8 r0 bottom
R18 "0R 0603" RESC0603(1608)_N 4102.75,1031.5 r90 top
R19 "RC0402FR-1310KL" RESC0402(1005)_L -305.12,903.6 r0 top value=10k
R20 "RC0402FR-1310KL" RESC0402(1005)_L -304.81,939.96 r0 top value=10k
R21 "RC0402FR-1310KL" RESC0402(1005)_L -304.81,977.36 r0 top value=10k
R22 "RC0402FR-1310KL" RESC0402(1005)_L -304.81,1013.78 r0 top value=10k
R23 "RC0402FR-1310KL" RESC0402(1005)_L -305.12,1050.2 r0 top value=10k
R24 "2.05k 0603" RESC0603(1608)_N 5141.73,1350.39 r0 bottom
R25 "22R 0402" RESC0402(1005)_L 1545.91,1433.65 r90 top
R26 "49.9R 0402" RESC0402(1005)_L 1608.73,1433.65 r270 top
R27 "0R 0402" RESC0402(1005)_L -386,1294 r90 bottom
R28 "10K 0402" RESC0402(1005)_N 226.42,1203.3 r270 bottom
R29 "10K 0402" RESC0402(1005)_N 1515.75,1208.66 r90 bottom
R30 "49.9R 0402" RESC0402(1005)_L 1514.2,1433.61 r270 top
R31 "RC0402FR-1310KL" RESC0402(1005)_L 1607,740 r90 top value=10k
R32 "CRCW04020000Z0ED" RESC0402(1005)_N 1608,817 r90 top value=0
R33 "300K 0402" RESC0402(1005)_L 5047.24,618.41 r270 top
R34 "47K 0402" RESC0402(1005)_L 5047.24,682.98 r270 top
R35 "10K 0402" RESC0402(1005)_L 6399.75,599.41 r90 top
R36 "10K 0402" RESC0402(1005)_L 6366.29,599.41 r90 top
R37 "10K 0402" RESC0402(1005)_L 5796.86,974.41 r270 top
R38 "0R 0603" RESC0603(1608)_L 2402,608.49 r90 top
R39 "22R 0603" RESC0603(1608)_L 1027.56,1011.81 r0 bottom
R40 "10K 0402" RESC0402(1005)_L 495.79,599.41 r90 top
R41 "10K 0402" RESC0402(1005)_L 172.6,595.47 r270 top
R42 "10K 0402" RESC0402(1005)_L 461.19,599.41 r90 top
R43 "10K 0402" RESC0402(1005)_L 740.89,1036.14 r90 top
R44 "CRCW04020000Z0ED" RESC0402(1005)_L -262.8,1134.84 r270 top value=0R
R45 "CRCW04020000Z0ED" RESC0402(1005)_L -294.29,1134.84 r270 top value=0R
R46 "10K 0402" RESC0402(1005)_N 1427.05,1042.91 r180 bottom
R47 "1M 0402" RESC0402(1005)_N 1662.4,1090.98 r0 top
R48 "2.49K 0402" RESC0402(1005)_N 1760.83,1091.54 r90 top
R49 "10K 0402" RESC0402(1005)_N 1429.13,1266.18 r180 bottom
R50 "10K 0402" RESC0402(1005)_N 1338.19,1266.18 r180 bottom
R51 "65.3k 0402" RESC0402(1005)_L 5047.24,804.44 r270 top
R52 "39.2k 0402" RESC0402(1005)_L 5047.24,869.69 r270 top
R53 "1K 0402" RESC0402(1005)_N 1657.48,748.03 r270 top
R54 "10K 0402" RESC0402(1005)_L 2173.99,599.18 r270 top
R55 "1K 0402" RESC0402(1005)_N 1779.53,744.09 r90 top
R56 "1K 0402" RESC0402(1005)_N 1717.63,744.09 r270 top
R57 "470R 0402" RESC0402(1005)_N 1841.97,744.09 r270 top
R58 "470R 0402" RESC0402(1005)_N 3068.02,606.24 r0 top
R59 "470R 0402" RESC0402(1005)_N 3068.02,644.41 r0 top
R60 "10K 0402" RESC0402(1005)_L 2141.46,599.18 r90 top
R61 "10K 0402" RESC0402(1005)_L 2451,612 r270 top
R62 "1K 0402" RESC0402(1005)_L 1307.09,1006.45 r90 top
R63 "ERJ2RKF7500X" RESC1005X40X25NL05T05 2751.97,706.69 r180 bottom value=750
R64 "CRCW04021K20FKED" RESC1005X40X25NL05T05 2845.47,706.69 r180 bottom value=1.2k
R65 "RC0402FR-07150RL" RESC1005X40X25NL05T10 2930.12,706.69 r180 bottom value=150
R66 "0R 0402" RESC0402(1005)_N 1311.02,956.69 r0 top
R67 "0R 0402" RESC0402(1005)_N 1307.09,1078.74 r270 top
R68 "RC0402FR-1310KL" RESC0402(1005)_L -226.38,1086.61 r0 top value=10k
R69 "100K 0402" RESC0402(1005)_L 4807.09,630.39 r180 top
R70 "10K 0402" RESC0402(1005)_L 2432.2,836.76 r180 bottom
R71 "10K 0402" RESC0402(1005)_L 6078.82,599.41 r270 top
R72 "RC0402FR-072K2L" RESC0402(1005)_L 1299,790 r0 top value=2.2k
R73 "RC0402FR-072K2L" RESC0402(1005)_L 1299,753 r0 top value=2.2k
R74 "0R 0603" RESC0603(1608)_L 4477,922.09 r90 bottom
R75 "0R 0603" RESC0603(1608)_L 6328.45,585.47 r90 top
R76 "470R 0402" RESC0402(1005)_L 4635,846.86 r0 bottom
R77 "0R 0603" RESC0603(1608)_L 422.01,586.13 r90 top
R78 "17.8K 0402" RESC0402(1005)_L 4579.56,846.46 r90 bottom
R79 "10K 0402" RESC0402(1005)_N -154,1224 r90 bottom
R80 "CRCW04020000Z0ED" RESC0402(1005)_L -232.28,1134.84 r270 top value=0R
R81 "RC0402FR-1310KL" RESC0402(1005)_L -305.12,1087.01 r0 top value=10k
R82 "CRCW04020000Z0ED" RESC0402(1005)_L 1012.28,1074.72 r90 bottom value=0R
R83 "CRCW04020000Z0ED" RESC0402(1005)_L 936,950.28 r270 bottom value=0R
R128 "10K 0402" RESC0402(1005)_L -228.56,1521.62 r0 top
R129 "10K 0402" RESC0402(1005)_L -229.33,1489.17 r0 top
R130 "10K 0402" RESC0402(1005)_L -228.35,1554.35 r0 top
R131 "1K 0402" RESC0402(1005)_L -169.29,1367.87 r270 top
R132 "10K 0402" RESC0402(1005)_L -291.56,1521.62 r0 top
R133 "10K 0402" RESC0402(1005)_L -292.32,1489.17 r0 top
R134 "10K 0402" RESC0402(1005)_L -291.34,1554.35 r0 top
R135 "10K 0402" RESC0402(1005)_L 6111.19,599.41 r270 top
R136 "10K 0402" RESC0402(1005)_L 206.21,595.47 r270 top
R183 "10K 0402" RESC0402(1005)_N 4704.72,634.68 r90 top
R185 "10K 0402" RESC0402(1005)_N 3928.58,713.68 r270 bottom
R186 "10K 0402" RESC0402(1005)_N 3933.54,957.58 r90 bottom
R187 "1.8MR 0402" RESC0402(1005)_N 4103.5,588.58 r180 bottom
R190 "1.8MR 0402" RESC0402(1005)_N 4184.06,589.57 r180 bottom
R213 "RC0402FR-1310KL" RESC0402(1005)_N 3862.65,608.16 r180 bottom
R214 "RC0402FR-1310KL" RESC0402(1005)_N 3862.65,649.5 r180 bottom
SW1 "434331045822" 434331045822 4051.24,551.18 r0 top
SW2 "434331045822" 434331045822 584,1564 r0 bottom
T1 "749119950" 749119950 4672.8,1338.58 r90 top locked
TP1 "TP100_200_NS" TP100_200_NS -359.26,1353.94 r0 top
TP2 "TP100_200_NS" TP100_200_NS -358.27,1273.62 r0 top
TP3 "TP100_200_NS" TP100_200_NS 2004.92,1149.61 r180 bottom
TP4 "TP100_200_NS" TP100_200_NS 4937.01,848.29 r0 top
TP5 "TP100_200_NS" TP100_200_NS 4094.49,1534.15 r0 top
TP6 "TP100_200_NS" TP100_200_NS 5456.69,1204.72 r0 top
TP7 "TP100_200_NS" TP100_200_NS 5307.09,551.18 r0 top
TP8 "TP100_200_NS" TP100_200_NS 4285.29,1158.46 r180 bottom
TP9 "TP100_200_NS" TP100_200_NS 5716.54,1468.5 r0 top
TP10 "TP100_200_NS" TP100_200_NS 3870.08,1257.32 r90 top
TP11 "TP100_200_NS" TP100_200_NS 3968.5,1000.27 r90 top
TP12 "TP100_200_NS" TP100_200_NS 4307.09,1035.43 r90 top
TP13 "TP100_200_NS" TP100_200_NS 4200.79,1058.33 r90 bottom
TP14 "TP100_200_NS" TP100_200_NS 6181.1,590.55 r90 top
TP15 "TP100_200_NS" TP100_200_NS 6259.84,590.55 r90 top
TP16 "TP100_200_NS" TP100_200_NS 5639,677 r90 top
TP17 "TP100_200_NS" TP100_200_NS 4806.1,862.2 r90 bottom
TP18 "TP100_200_NS" TP100_200_NS 271.8,581.69 r90 top
TP19 "TP100_200_NS" TP100_200_NS 5704.72,1236.22 r90 bottom
TP20 "TP100_200_NS" TP100_200_NS 4691.93,881.89 r90 top
TP21 "TEST_POINT" TP075_150_NS 3852.21,640 r90 top
TP22 "TP100_200_NS" TP100_200_NS 934.06,897.24 r90 top
TP23 "TP100_200_NS" TP100_200_NS 5688.98,868.6 r90 top
TP24 "TP100_200_NS" TP100_200_NS 5311.02,730.62 r90 top
TP25 "TEST_POINT" TP075_150_NS 4089.11,661.24 r270 bottom
TP26 "TEST_POINT" TP100_200_NS 1537,862.91 r90 top
TP27 "TP100_200_NS" TP100_200_NS 1231,550 r90 top
TP28 "TP100_200_NS" TP100_200_NS 1319,550 r90 top
TP29 "TP100_200_NS" TP100_200_NS 1144,550 r90 top
TP30 "TP100_200_NS" TP100_200_NS 1079.49,1129.92 r90 bottom
TP31 "TP100_200_NS" TP100_200_NS 354.18,581.57 r90 top
TP32 "TP100_200_NS" TP100_200_NS 2232.28,594.49 r90 top
TP33 "TP100_200_NS" TP100_200_NS 2318.9,594.49 r90 top
TP34 "TEST_POINT" TP100_200_NS 1396,862.91 r90 top
TP35 "TEST_POINT" TP100_200_NS 1311.02,861.91 r90 top
TP41 "TEST_POINT" TP075_150_NS 3852,703 r90 top
U1 "SI3404-A-GM" Si3404-A-GM 4114.3,1200.79 r270 top
U2 "VO618A-3X017T" VO618A-3X017T 4794.85,1169.29 r180 bottom
U3 "TLV62080DSG" TLV62080DSG 5125.98,667.62 r0 top
U4 "RTL8111HS-CG" RTL8111Hx-CG 1635.14,1245.04 r180 top
U5 "TLV431" TLV431BCDBZR 4873.85,1348.43 r180 bottom
U6 "TXS0102DCU" TXS0102DCUR 1371.93,1153.14 r90 bottom
U7 "24AA32A-I/MS 8-MSOP" 24AA32A-I/MS -255.91,1318.9 r270 top
U8 "LM66100DCKR" LM66100DCKR 4807.09,690.94 r0 top
U9 "BMI270" XDCR_BMI270 2585.79,923.23 r270 bottom
U10 "TLV70018DCK" TLV70018DCK 5465.55,638.94 r270 top
U11 "BNO085" BNO085 1455,717.52 r270 top locked
U14 "NCP114AMX280TCG" FP-517CU-MFG 5451.53,836.61 r90 top
U15 "TLV62080DSG" TLV62080DSG 5125.98,854.33 r0 top
U61 "CBTL02043A" CBTL02043A 4017.36,836.9 r0 bottom
U62 "PTN5150AHXMP" PTN5150H 4013.45,645.96 r180 bottom
X1 "25MHz 18pF 2.50x2.00mm" ECS-250-18-36B-CKY-TR 1662.7,966.45 r0 top
Y1 "ABS06-127-32.768KHZ-T" ABS06-127-32.768KHZ-T 1483.29,548.35 r180 top

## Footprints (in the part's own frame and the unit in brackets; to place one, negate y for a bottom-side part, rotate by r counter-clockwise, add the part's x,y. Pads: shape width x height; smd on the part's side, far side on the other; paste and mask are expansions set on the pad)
1N4148W-7-F [mm] "SOD123, 2-Leads, Body 2.7x1.55mm, Height 1.45mm"
  rect 0.9x0.95 smd: 1(-1.575,0) 2(1.575,0)
  silkscreen extent -2.4,-0.87 0,0.87, body extent -1.35,-0.77 1.35,0.77, height 1.45
24AA32A-I/MS [mm] "Body: 3 x 3mm, pitch: 0.65mm"
  rect 1.4x0.35 smd mask+0.05: 1(-2.2,0.975)
  oval 1.4x0.35 smd mask+0.05: 2(-2.2,0.325) 3(-2.2,-0.325) 4(-2.2,-0.975) 5(2.2,-0.975) 6(2.2,-0.325) 7(2.2,0.325) 8(2.2,0.975)
  silkscreen extent -2.32,-1.5 1.2,1.73, body extent -2.45,-1.5 2.45,1.5, height 1.15
104031-0811 [mm] "10 (8 + 2) Position Card Connector Secure Digital - microSD?Surface Mount, Right Angle Gold"
  rect 0.85x1.1 smd: 1(3.113,-5.412) 3(0.913,-5.412) 4(-0.188,-5.412) 5(-1.288,-5.412) 6(-2.387,-5.412) 7(-3.487,-5.412)
  rect 0.875x1.1 smd: 2(2.013,-5.412)
  rect 0.75x1.1 smd: 8(-4.537,-5.412)
  rect 1.2x1 smd: 9(5.748,0.738) 10(5.748,4.438)
  rect 1.9x1.35 smd: 11(2.248,5.413) 12(-3.722,5.413)
  rect 1.17x1.8 smd: 13(-5.747,-5.062)
  rect 1.55x1.35 smd: 14(5.573,-5.287)
  body extent -5.95,-5.65 6,5.75, height 1.44
20021121-00010T1LF [mm] "Connector Header Surface Mount 10 position 0.050\" (1.27mm)   Contact length: 0.120\" (3.05mm)"
  rect 0.76x2.4 smd: 1(-2.54,-1.95) 2(-2.54,1.95) 3(-1.27,-1.95) 4(-1.27,1.95) 5(0,-1.95) 6(0,1.95) 7(1.27,-1.95) 8(1.27,1.95) 9(2.54,-1.95) 10(2.54,1.95)
  body extent -3.18,-2.75 3.17,2.75, height 4.55
742792040 [mm] "Chip Inductor, 2-Leads, Body 2.0x1.2mm"
  rect 1x1 smd: 1(-1.1,0) 2(1.1,0)
  silkscreen extent -0.2,-0.6 0.2,0.6, body extent -1,-0.6 1,0.6, height 0.89
749119950 [mm] "SMD, 10-Leads, Body 13.5x14.0mm (max), Pitch 2.48mm, IPC Medium Density"
  rect 1.27x1.55 smd: 1(-5,8.275) 2(-2.5,8.275) 3(0,8.275) 4(2.5,8.275) 5(5,8.275) 6(5,-8.275) 7(2.5,-8.275) 8(0,-8.275) 9(-2.5,-8.275) 10(-5,-8.275)
  silkscreen extent -6.75,-6.75 6.75,8.25, body extent -6.75,-8.88 6.75,8.87, height 12.6
2508056017Y2 [mm] "2508056017Y2 Chip Inductor, 2-Leads, Body 2.00x1.25mm"
  rect 1.3x1.5 smd: 1(-0.95,0) 2(0.95,0)
  body extent -1.1,-0.72 1.1,0.73, height 1.45
9774030243R [mm] "STANDOFF_M2X0.4_3MM with no pad on bottom of PCB"
  round 5.3 / inner round 2.7 / far side round 2.7 hole 3 mask+0.05: 1(0,0)
  body extent -2.17,-2.16 2.18,2.16, height 3.05
61000418321 [mm] "Pin Header, pitch 2.54 mm, SMD, Vertical, single row, 4p"
  rect 1x3 smd: 1(-3.81,1.5) 2(-1.27,-1.5) 3(1.27,1.5) 4(3.81,-1.5)
  silkscreen extent -5.23,-1.34 5.23,1.35, body extent -5.08,-2.5 5.08,2.5, height 9.37
434331045822 [mm] "4.7*3.5mm side push type,SMD, height 1.65mm, black actuator, 220gf, T&R"
  rect 1.2x1 smd: 1(2.8,0.85) 2(2.8,-0.85) 3(-2.8,0.85) 4(-2.8,-0.85)
  silkscreen extent -2.35,-2.75 2.35,1.75, body extent -3.2,-2.75 3.2,1.75, height 1.65
632723100011 [mm] "USB 3.1 Type C Receptacle Horizontal THR"
  rect 0.3x1.2 smd: A1(-2.75,5.93) A2(-2.25,5.93) A3(-1.75,5.93) A4(-1.25,5.93) A5(-0.75,5.93) A6(-0.25,5.93) A7(0.25,5.93) A8(0.75,5.93) A9(1.25,5.93) A10(1.75,5.93) A11(2.25,5.93) A12(2.75,5.93)
  round 0.65 hole 0.4: B1(2.8,4.68) B2(2.4,3.98) B3(1.6,3.98) B4(1.2,4.68) B5(0.8,3.98) B6(0.4,4.68) B7(-0.4,4.68) B8(-0.8,3.98) B9(-1.2,4.68) B10(-1.6,3.98) B11(-2.4,3.98) B12(-2.8,4.68) G1(2,4.68) G2(-2,4.68)
  oval 1x1.6 hole 0.6 slot 1.2 at 90 deg: Shell(-4.27,-1.2) Shell(-4.27,3.53) Shell(4.27,-1.2) Shell(4.27,3.53)
  rect 0.2x1 smd: Shell(0,-1.75) Shell(0,1.35)
  silkscreen extent -4.37,-4.45 4.34,5, body extent -4.37,-5.6 4.37,6.19, height 3.05
ABS06-127-32.768KHZ-T [mm] "2-SMD 0.079\" L x 0.047\" W (2.00mm x 1.20mm)"
  rect 0.75x1.4 smd: 1(-0.73,0) 2(0.73,0)
  body extent -1,-0.6 1,0.6, height 0.65
AC-PY003-OV9282 [mm] "connector: FH26W-33S-0.3SHW"
  rect 0.4x0.95 smd mask+0.05: 0(-5.488,-8.984) 0(5.512,-8.984)
  rect 0.3x0.65 smd mask+0.05: 1(4.812,-8.634) 2(4.52,-11.084) 3(4.212,-8.634) 4(3.92,-11.084) 5(3.612,-8.634) 6(3.32,-11.084) 7(3.012,-8.634) 8(2.72,-11.084) 9(2.412,-8.634) 10(2.12,-11.084) 11(1.812,-8.634) 12(1.52,-11.084) 13(1.212,-8.634) 14(0.92,-11.084) 15(0.612,-8.634) 16(0.32,-11.084) 17(0.012,-8.634) 18(-0.28,-11.084) 19(-0.588,-8.634) 20(-0.88,-11.084) 21(-1.188,-8.634) 22(-1.48,-11.084) 23(-1.788,-8.634) 24(-2.08,-11.084) 25(-2.388,-8.634) 26(-2.68,-11.084) 27(-2.988,-8.634) 28(-3.28,-11.084) 29(-3.588,-8.634) 30(-3.88,-11.084) 31(-4.188,-8.634) 32(-4.48,-11.084) 33(-4.788,-8.634)
  Top Copper keep-out region: -4.2,-4.2 4.3,-4.2 4.3,4.2 -4.2,4.2
  Top Copper keep-out region: -5.688,-10.602 5.73,-10.602 5.73,-9.573 -5.688,-9.573
  Top Copper keep-out region: -5.088,-7.981 5.131,-7.981 5.131,-7.138 -5.088,-7.138
  silkscreen extent -6.5,-11.68 6.52,6.39, body extent -5.69,-11.43 5.71,5.1, height 5.6
BNO085 [mm] "28-TFLGA Module (5.2x3.8)"
  rect 0.675x0.25 smd paste+0 mask+0: 1(1.562,2.25) 6(-1.562,2.25) 7(-1.562,1.75) 8(-1.562,1.25) 9(-1.562,0.75) 10(-1.562,0.25) 11(-1.562,-0.25) 12(-1.562,-0.75) 13(-1.562,-1.25) 14(-1.562,-1.75) 15(-1.562,-2.25) 20(1.562,-2.25) 21(1.562,-1.75) 22(1.562,-1.25) 23(1.562,-0.75) 24(1.562,-0.25) 25(1.562,0.25) 26(1.562,0.75) 27(1.562,1.25) 28(1.562,1.75)
  rect 0.25x0.575 smd paste+0 mask+0: 2(0.75,2.312) 3(0.25,2.312) 4(-0.25,2.312) 5(-0.75,2.312) 16(-0.75,-2.312) 17(-0.25,-2.312) 18(0.25,-2.312) 19(0.75,-2.312)
  silkscreen extent -2.3,-3.08 3.47,3.08, body extent -2.45,-3.15 2.45,3.15, height 0.25
CAPC0201(0603)33_L [mm] "Chip Capacitor, Body 0.6x0.3mm, Height 0.33mm, IPC High Density"
  rect 0.36x0.32 smd: 1(-0.28,0) 2(0.28,0)
  body extent -0.32,-0.17 0.32,0.17, height 0.33
CAPC0402(1005)60_N [mm] "Chip Capacitor, Body 1.0x0.5mm, Height 0.6mm, IPC Medium Density"
  rect 0.62x0.62 smd: 1(-0.45,0) 2(0.45,0)
  body extent -0.55,-0.3 0.55,0.3, height 0.6
CAPC0402(1005)70_L [mm] "Chip Capacitor, Body 1.0x0.5mm, Height 0.7mm, IPC High Density"
  rect 0.52x0.52 smd: 1(-0.4,0) 2(0.4,0)
  body extent -0.55,-0.3 0.55,0.3, height 0.7
CAPC0402(1005)70_N [mm] "Chip Capacitor, Body 1.0x0.5mm, Height 0.7mm, IPC Medium Density"
  rect 0.62x0.62 smd: 1(-0.45,0) 2(0.45,0)
  body extent -0.55,-0.3 0.55,0.3, height 0.7
CAPC0603(1608)100_L [mm] "Chip Capacitor, Body 1.6x0.8mm, Height 1.0mm, IPC High Density"
  rect 0.7x0.9 smd: 1(-0.7,0) 2(0.7,0)
  silkscreen extent -0.05,-0.35 0.05,0.35, body extent -0.87,-0.47 0.88,0.48, height 1
CAPC0603(1608)100_N [mm] "Chip Capacitor, Body 1.6x0.8mm, Height 1.0mm, IPC Medium Density"
  rect 0.9x1 smd: 1(-0.8,0) 2(0.8,0)
  silkscreen extent -0.05,-0.4 0.05,0.4, body extent -0.87,-0.48 0.88,0.47, height 1
CAPC0805(2012)145_N [mm] "Chip Capacitor, Body 2.0x1.2mm, Height 1.45mm, IPC Medium Density"
  rect 1.15x1.45 smd: 1(-0.9,0) 2(0.9,0)
  silkscreen extent -0.05,-0.62 0.05,0.63, body extent -1.1,-0.72 1.1,0.73, height 1.45
CAPC1206(3216)190_N [mm] "Chip Capacitor, Body 3.2x1.6mm, Height 1.9mm, IPC Medium Density"
  rect 1.15x1.8 smd: 1(-1.5,0) 2(1.5,0)
  silkscreen extent -0.55,-0.8 0.55,0.8, body extent -1.7,-0.9 1.7,0.9, height 1.9
CAPC1210(3225)280_N [mm] "Chip Capacitor, Body 3.2x2.5mm, Height 2.8mm, IPC Medium Density"
  rect 1.15x2.7 smd: 1(-1.5,0) 2(1.5,0)
  silkscreen extent -0.55,-1.25 0.55,1.25, body extent -1.7,-1.4 1.7,1.4, height 2.8
CBTL02043A [mm] "VQFN-20"
  rrect20% 0.25x0.6 smd mask+0.07: 1(-0.25,2.15) 10(-0.25,-2.15) 11(0.25,-2.15) 20(0.25,2.15)
  rrect20% 0.6x0.25 smd mask+0.07: 2(-1.15,1.75) 3(-1.15,1.25) 4(-1.15,0.75) 5(-1.15,0.25) 6(-1.15,-0.25) 7(-1.15,-0.75) 8(-1.15,-1.25) 9(-1.15,-1.75) 12(1.15,-1.75) 13(1.15,-1.25) 14(1.15,-0.75) 15(1.15,-0.25) 16(1.15,0.25) 17(1.15,0.75) 18(1.15,1.25) 19(1.15,1.75)
  rrect10% 1x3 smd paste-3 mask+0.07: 21(0,0)
  silkscreen extent -1.25,-2.25 1.25,2.53, body extent -1.25,-2.25 1.25,2.25, height 1
CD-H01 [mm] "2 mm SMD Trimming Potentiometer  Specifications are subject to change without notice.  Users should verify actual device performance in their specific applications.  The products described herein and this document are subject to specific legal disclaimers as set forth on the last page of this document, and at www.bourns.com/docs/legal/disclaimer.pdf.  CD-HD0x Series Surface Mount Schottky Bridge Rectifier Diode"
  rect 1.2x1.2 smd: 1(1.25,2.95) 2(1.25,-2.95) 3(-1.25,-2.95) 4(-1.25,2.95)
  silkscreen extent -2.35,-3.08 2.43,3.53, body extent -2.37,-3.08 2.37,3.08, height 1.14
CON_A_BW2099_SoM_DF40HC-3.0-100DS-0.4V_minpad [mm] "3.0MM MATED HEIGHT CONN HDR 100POS 0.4MM SMD GOLD"
  rect 0.7x0.18 smd: 1(-19.04,-9.8) 2(-15.96,-9.8) 3(-19.04,-9.4) 4(-15.96,-9.4) 5(-19.04,-9) 6(-15.96,-9) 7(-19.04,-8.6) 8(-15.96,-8.6) 9(-19.04,-8.2) 10(-15.96,-8.2) 11(-19.04,-7.8) 12(-15.96,-7.8) 13(-19.04,-7.4) 14(-15.96,-7.4) 15(-19.04,-7) 16(-15.96,-7) 17(-19.04,-6.6) 18(-15.96,-6.6) 19(-19.04,-6.2) 20(-15.96,-6.2) 21(-19.04,-5.8) 22(-15.96,-5.8) 23(-19.04,-5.4) 24(-15.96,-5.4) 25(-19.04,-5) 26(-15.96,-5) 27(-19.04,-4.6) 28(-15.96,-4.6) 29(-19.04,-4.2) 30(-15.96,-4.2) 31(-19.04,-3.8) 32(-15.96,-3.8) 33(-19.04,-3.4) 34(-15.96,-3.4) 35(-19.04,-3) 36(-15.96,-3) 37(-19.04,-2.6) 38(-15.96,-2.6) 39(-19.04,-2.2) 40(-15.96,-2.2) 41(-19.04,-1.8) 42(-15.96,-1.8) 43(-19.04,-1.4) 44(-15.96,-1.4) 45(-19.04,-1) 46(-15.96,-1) 47(-19.04,-0.6) 48(-15.96,-0.6) 49(-19.04,-0.2) 50(-15.96,-0.2) 51(-19.04,0.2) 52(-15.96,0.2) 53(-19.04,0.6) 54(-15.96,0.6) 55(-19.04,1) 56(-15.96,1) 57(-19.04,1.4) 58(-15.96,1.4) 59(-19.04,1.8) 60(-15.96,1.8) 61(-19.04,2.2) 62(-15.96,2.2) 63(-19.04,2.6) 64(-15.96,2.6) 65(-19.04,3) 66(-15.96,3) 67(-19.04,3.4) 68(-15.96,3.4) 69(-19.04,3.8) 70(-15.96,3.8) 71(-19.04,4.2) 72(-15.96,4.2) 73(-19.04,4.6) 74(-15.96,4.6) 75(-19.04,5) 76(-15.96,5) 77(-19.04,5.4) 78(-15.96,5.4) 79(-19.04,5.8) 80(-15.96,5.8) 81(-19.04,6.2) 82(-15.96,6.2) 83(-19.04,6.6) 84(-15.96,6.6) 85(-19.04,7) 86(-15.96,7) 87(-19.04,7.4) 88(-15.96,7.4) 89(-19.04,7.8) 90(-15.96,7.8) 91(-19.04,8.2) 92(-15.96,8.2) 93(-19.04,8.6) 94(-15.96,8.6) 95(-19.04,9) 96(-15.96,9) 97(-19.04,9.4) 98(-15.96,9.4) 99(-19.04,9.8) 100(-15.96,9.8)
  silkscreen extent -22.53,-15 -16.85,15.03, body extent -19.19,-11.3 -15.81,11.3, height 2.85
CON_B_BW2099_SoM_DF40HC-3.0-100DS-0.4V_minpad [mm] "3.0MM MATED HEIGHT CONN HDR 100POS 0.4MM SMD GOLD"
  rect 0.7x0.18 smd: 1(17.96,-6.8) 2(21.04,-6.8) 3(17.96,-6.4) 4(21.04,-6.4) 5(17.96,-6) 6(21.04,-6) 7(17.96,-5.6) 8(21.04,-5.6) 9(17.96,-5.2) 10(21.04,-5.2) 11(17.96,-4.8) 12(21.04,-4.8) 13(17.96,-4.4) 14(21.04,-4.4) 15(17.96,-4) 16(21.04,-4) 17(17.96,-3.6) 18(21.04,-3.6) 19(17.96,-3.2) 20(21.04,-3.2) 21(17.96,-2.8) 22(21.04,-2.8) 23(17.96,-2.4) 24(21.04,-2.4) 25(17.96,-2) 26(21.04,-2) 27(17.96,-1.6) 28(21.04,-1.6) 29(17.96,-1.2) 30(21.04,-1.2) 31(17.96,-0.8) 32(21.04,-0.8) 33(17.96,-0.4) 34(21.04,-0.4) 35(17.96,0) 36(21.04,0) 37(17.96,0.4) 38(21.04,0.4) 39(17.96,0.8) 40(21.04,0.8) 41(17.96,1.2) 42(21.04,1.2) 43(17.96,1.6) 44(21.04,1.6) 45(17.96,2) 46(21.04,2) 47(17.96,2.4) 48(21.04,2.4) 49(17.96,2.8) 50(21.04,2.8) 51(17.96,3.2) 52(21.04,3.2) 53(17.96,3.6) 54(21.04,3.6) 55(17.96,4) 56(21.04,4) 57(17.96,4.4) 58(21.04,4.4) 59(17.96,4.8) 60(21.04,4.8) 61(17.96,5.2) 62(21.04,5.2) 63(17.96,5.6) 64(21.04,5.6) 65(17.96,6) 66(21.04,6) 67(17.96,6.4) 68(21.04,6.4) 69(17.96,6.8) 70(21.04,6.8) 71(17.96,7.2) 72(21.04,7.2) 73(17.96,7.6) 74(21.04,7.6) 75(17.96,8) 76(21.04,8) 77(17.96,8.4) 78(21.04,8.4) 79(17.96,8.8) 80(21.04,8.8) 81(17.96,9.2) 82(21.04,9.2) 83(17.96,9.6) 84(21.04,9.6) 85(17.96,10) 86(21.04,10) 87(17.96,10.4) 88(21.04,10.4) 89(17.96,10.8) 90(21.04,10.8) 91(17.96,11.2) 92(21.04,11.2) 93(17.96,11.6) 94(21.04,11.6) 95(17.96,12) 96(21.04,12) 97(17.96,12.4) 98(21.04,12.4) 99(17.96,12.8) 100(21.04,12.8)
  silkscreen extent 16.75,-15.04 22.53,15, body extent 17.81,-8.3 21.19,14.3, height 2.85
DDTC114YCA-7-F [mm] "TO-236-3, SC-59, SOT-23-3"
  rect 0.8x0.9 smd: 1(-0.95,-1) 2(0.95,-1) 3(0,1)
  silkscreen extent -1.46,0 1.46,0.69, body extent -1.5,-1.1 1.5,1.1, height 1.1
DFE252012P-1R0M=P2 [mm] "Chip Inductor, 2-Leads, Body 2.40x2.00mm, IPC High Density"
  rect 0.8x2 smd: 1(-1,0) 2(1,0)
  silkscreen extent -0.05,-0.9 0.05,0.9, body extent -1.25,-1.1 1.25,1.1, height 1.2
DO1608C-102MLx [mm] "Coil inductor 6.6x4.45mm"
  rect 1.4x3.56 smd: 1(-2.73,0) 2(2.73,0)
  silkscreen extent -2.01,-2.22 2.01,2.22, body extent -3.3,-2.23 3.3,2.22, height 2.92
DTSM-32N-V [mm] "tactile button 160gf"
  rect 2x1.5 smd: 1(-2.7,0) 2(2.7,0)
  silkscreen extent -3.01,-1.76 3,1.75, body extent -3.65,-1.75 3.65,1.75, height 5
ECA-0JM102 [mm] "Body diameter: 8mm, lead pitch: 3.5mm"
  rect 1.6x1.6 / inner round 1.6 / far side rect 1.6x1.6 hole 0.8 mask+0.05: 1(-1.75,0)
  round 1.6 hole 0.8 mask+0.05: 2(1.75,0)
  silkscreen extent -4.15,-4 4,4.4, body extent -4,-4 4,4, height 16
ECS-250-18-36B-CKY-TR [mm] "2.5x2.0mm ceramic SMD"
  rect 1.2x1 smd: 1(-0.85,-0.65) 2(0.85,-0.65) 3(0.85,0.65) 4(-0.85,0.65)
  silkscreen extent -1.77,-1.44 1.75,0.99, body extent -1.3,-1.05 1.3,1.05, height 0.6
EEU-FC2A120 [mm] "Body diameter: 6.3mm, lead pitch: 2.5mm"
  rect 1.6x1.6 / inner round 1.6 / far side rect 1.6x1.6 hole 0.8 mask+0.05: 1(-1.25,0)
  round 1.6 hole 0.8 mask+0.05: 2(1.25,0)
  silkscreen extent -3.6,-3.15 3.15,3.6, body extent -3.15,-3.15 3.15,3.15, height 12
FIDUCIAL_ROUND_1MM [mm] "Round, 1mm dia"
  round 1 smd paste-1 mask+0.5: 1(0,0)
  Top Copper keep-out circle w0.025: c0,0 r1
FP-517CU-MFG [mil]
  round 1 smd: 1(-12.8,-15.26) 2(12.8,-17.24) 3(12.8,17.24) 4(-12.8,17.24)
  rect 22.83x22.83 smd rot 135 paste+0 mask+0: 5(0,0)
  Top Copper region: -18.7,8.78 -18.7,25.71 -6.89,25.71 -6.89,16.65 -14.76,8.78
  Top Copper region: -18.7,-25.69 -18.7,-4.82 -6.89,-16.63 -6.89,-25.69
  Top Copper region: 18.7,-8.78 18.7,-25.71 6.89,-25.71 6.89,-16.65 14.76,-8.78
  Top Copper region: 18.7,25.71 6.89,25.71 6.89,16.65 14.76,8.78 18.7,8.78
  silkscreen extent -33,-54 33,21, body extent -25,-30 25,30, height 10
FP-155124M173200-MFG [mm]
  rect 0.6x0.9 smd paste+0 mask+0: 1(-1.4,0.5) 4(1.4,0.5)
  rect 0.6x0.55 smd paste+0 mask+0: 2(-0.45,0.825) 3(0.45,0.825)
  silkscreen extent -2.37,-0.8 1.65,0.62, body extent -1.8,-0.9 1.8,1.2, height 0.25
LM66100DCKR [mm] "SOT23, 6-Leads, Body 2.00x2.10mm, Pitch 0.65mm, IPC Medium Density"
  rect 0.85x0.35 smd: 1(-1.1,0.65) 2(-1.1,0) 3(-1.1,-0.65) 4(1.1,-0.65) 5(1.1,0) 6(1.1,0.65)
  silkscreen extent -1.42,-1.1 0.3,1.46, body extent -1.2,-1.07 1.2,1.07, height 1.1
LQH32NH2R2J23L [mm] "inductor 3.20mm x 2.50mm x 2.2mm"
  rect 1x2 smd: 1(-1.15,0) 2(1.15,0)
  Top Copper region: -1.15,-0.45 -2.7,-0.45 -2.7,0.45 -1.15,0.45
  Top Copper region: 1.15,0.45 2.75,0.45 2.75,-0.45 1.15,-0.45
  body extent -1.6,-1.25 1.6,1.25, height 1.55
ONSC-SC70-6-419B-02_W_V [mm] "SOT23, 6-Leads, Body 2x1.25mm, Pitch 0.65mm"
  rect 0.5x0.4 smd: 1(-0.95,0.65) 2(-0.95,0) 3(-0.95,-0.65) 4(0.95,-0.65) 5(0.95,0) 6(0.95,0.65)
  silkscreen extent -1.08,-1 0.3,1.52, body extent -1.05,-1 1.05,1, height 1.08
PDS1040-13 [mm] "Powerdi5 Diodes"
  rect 4.86x3.36 smd: 1(-1.126,0)
  rect 1.4x1.39 smd: 2(2.856,-0.92) 2(2.856,0.92)
  silkscreen extent -3.9,-1.68 -3.9,1.68, body extent -3.25,-1.99 3.25,1.99, height 1.12
PTN5150H [mm] "X2QFN-12 1.6x1.6"
  rrect50% 0.2x0.7 smd mask+0.05: 1(0.2,0.65) 2(-0.2,0.65) 7(-0.2,-0.65) 8(0.2,-0.65)
  rrect50% 0.5x0.2 smd mask+0.05: 3(-0.75,0.6) 4(-0.75,0.2) 5(-0.75,-0.2) 6(-0.75,-0.6) 9(0.75,-0.6) 10(0.75,-0.2) 11(0.75,0.2) 12(0.75,0.6)
  silkscreen extent 0.57,0.97 0.63,1.03, body extent -0.8,-0.8 0.8,0.8, height 0.4
RE1C002UNTCL [mm] "ROHM SOT-416FL"
  rect 0.3x0.71 smd: 1(-0.5,-0.61) 2(0.5,-0.61) 3(0,0.61)
  silkscreen extent -0.85,0.18 0.85,0.48, body extent -0.95,-1.06 0.95,1.07, height 0.25
RESC0402(1005)_L [mm] "Chip Resistor, Body 1.0x0.5mm, IPC High Density"
  rect 0.45x0.55 smd: 1(-0.45,0) 2(0.45,0)
  body extent -0.52,-0.27 0.53,0.28, height 0.4
RESC0402(1005)_N [mm] "Chip Resistor, Body 1.0x0.5mm, IPC Medium Density"
  rect 0.55x0.65 smd: 1(-0.5,0) 2(0.5,0)
  body extent -0.52,-0.27 0.53,0.28, height 0.4
RESC0603(1608)_L [mm] "Chip Resistor, Body 1.6x0.8mm, IPC High Density"
  rect 0.7x0.9 smd: 1(-0.7,0) 2(0.7,0)
  silkscreen extent -0.05,-0.35 0.05,0.35, body extent -0.85,-0.47 0.85,0.47, height 0.6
